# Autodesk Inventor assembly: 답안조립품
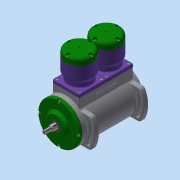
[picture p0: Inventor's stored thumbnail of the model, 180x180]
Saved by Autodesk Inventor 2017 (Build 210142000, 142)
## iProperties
Part Number: 답안조립품
Material: 일반
Document SubType Name: Assembly
Designer: Administrator
Mass: 7371.37 g
Surface Area: 5215.2 cm^2
Volume: 2062.19 cm^3
Density: 3.57453 g/cm^3
Author: Administrator
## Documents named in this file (16)
- C:\Users\Administrator\Desktop\620106V1021\답안조립품.iam
- C:\Users\Administrator\Desktop\620106V1021\너트 M4.ipt
- C:\Users\Administrator\Desktop\620106V1021\베어링 6303.ipt
- C:\Users\Administrator\Desktop\620106V1021\본체.ipt
- C:\Users\Administrator\Desktop\620106V1021\볼트 M4 x 12.ipt
- C:\Users\Administrator\Desktop\620106V1021\볼트 M5 x 20.ipt
- C:\Users\Administrator\Desktop\620106V1021\실린더.ipt
- C:\Users\Administrator\Desktop\620106V1021\실린더헤드.ipt
- C:\Users\Administrator\Desktop\620106V1021\앞커버.ipt
- C:\Users\Administrator\Desktop\620106V1021\오일 실 17 x 32 x 8.ipt
- C:\Users\Administrator\Desktop\620106V1021\육각 머리 볼트 M4 x 16.ipt
- C:\Users\Administrator\Desktop\620106V1021\커넥팅로드 엔드.ipt
- C:\Users\Administrator\Desktop\620106V1021\커넥팅로드.ipt
- C:\Users\Administrator\Desktop\620106V1021\크랭크축.ipt
- C:\Users\Administrator\Desktop\620106V1021\피스톤.ipt
- C:\Users\Administrator\Desktop\620106V1021\피스톤핀.ipt
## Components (4 placed, 2 different names)
1. 피스톤:1
2. 피스톤핀:1
3. 피스톤:2
4. 피스톤핀:2
